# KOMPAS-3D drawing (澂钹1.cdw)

Views: Вид 1
Referenced files in D:\Проекты\2019\июнь\Autor24\4102158_21_2019\: Эпюр1.cdw
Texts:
  Вариант №5
  Эпюр №1
  Лукьянов А.С.
  ISOCPEUR
  Стили документа
  Вариант №5-
Dimensions and other numbers on the sheet: 1; 2; 3; 4; 1:1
